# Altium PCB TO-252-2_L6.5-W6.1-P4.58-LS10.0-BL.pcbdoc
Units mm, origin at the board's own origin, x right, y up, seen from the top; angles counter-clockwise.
Board outline 19.26 x 24.24 mm, 2 copper layers (Top Layer, Bottom Layer), stack 0 mm thick; 1 components, 0 nets, 3 pads, 0 vias.
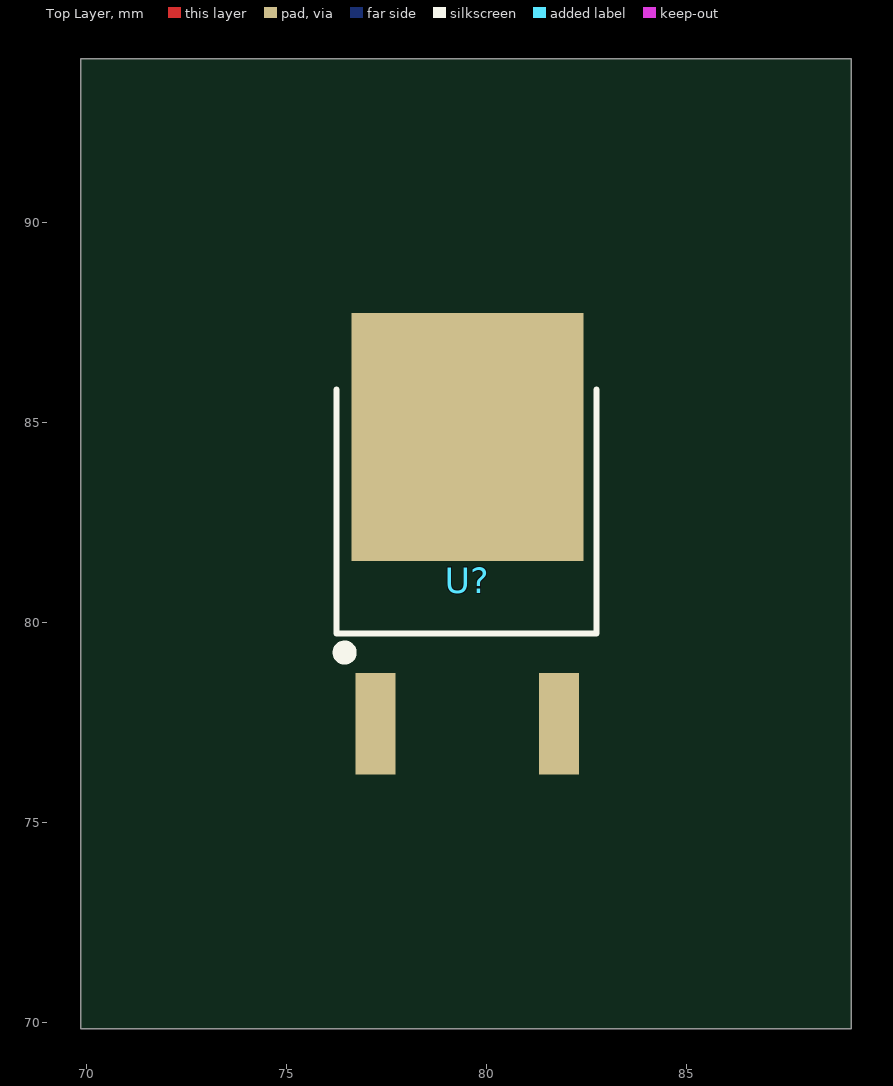
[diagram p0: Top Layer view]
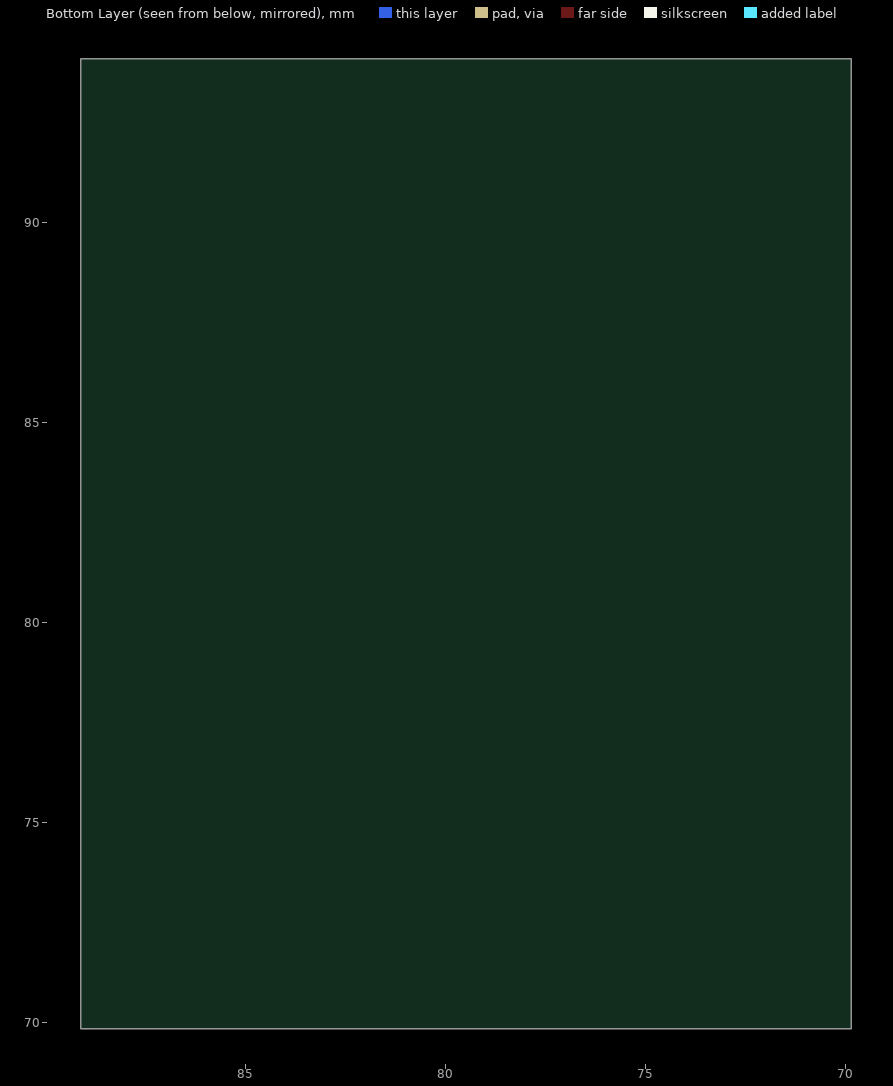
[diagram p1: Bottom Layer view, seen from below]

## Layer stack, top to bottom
Top Layer: signal copper (thickness not stored)
Bottom Layer: signal copper (thickness not stored)

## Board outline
89.11,69.85 69.85,69.85 69.85,94.094 89.11,94.094

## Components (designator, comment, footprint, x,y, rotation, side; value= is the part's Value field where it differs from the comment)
U? "" TO-252-2_L6.5-W6.1-P4.58-LS10.0-BL 79.51,81.057 r0 top

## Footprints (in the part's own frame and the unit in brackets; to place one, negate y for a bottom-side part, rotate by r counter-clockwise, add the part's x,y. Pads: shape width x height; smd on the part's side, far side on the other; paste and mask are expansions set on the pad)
TO-252-2_L6.5-W6.1-P4.58-LS10.0-BL [mm]
  rect 1x2.54 smd paste+0 mask+0.05: 1(-2.29,-3.587) 3(2.29,-3.587)
  rect 5.8x6.2 smd paste+0 mask+0.05: 2(0,3.587)
  silkscreen extent -3.26,-1.95 3.24,4.77

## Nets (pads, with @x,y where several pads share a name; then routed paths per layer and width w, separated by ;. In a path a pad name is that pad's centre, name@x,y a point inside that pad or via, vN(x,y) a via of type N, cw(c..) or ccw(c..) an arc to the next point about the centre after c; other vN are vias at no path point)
pads on no net: U?.1 U?.2 U?.3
